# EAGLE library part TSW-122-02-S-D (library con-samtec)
THROUGH-HOLE .025" SQ POST HEADER Source: Samtec TSW.pdf
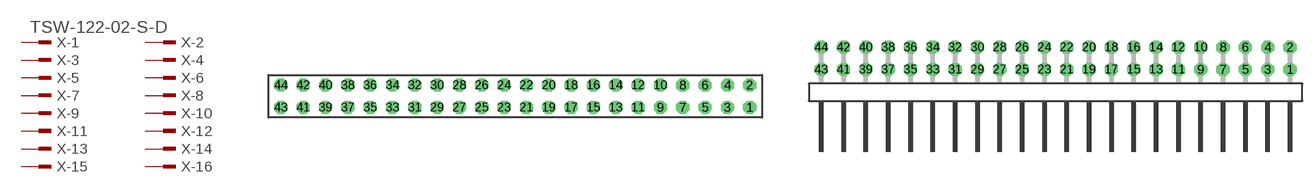
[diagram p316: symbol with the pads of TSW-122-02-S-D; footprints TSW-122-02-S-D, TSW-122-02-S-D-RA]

Designator prefix X; gates -1=MPINV -2=MPIN -3=MPIN -4=MPIN -5=MPIN -6=MPIN -7=MPIN -8=MPIN -9=MPIN -10=MPIN -11=MPIN -12=MPIN -13=MPIN -14=MPIN -15=MPIN -16=MPIN -17=MPIN -18=MPIN -19=MPIN -20=MPIN -21=MPIN -22=MPIN -23=MPIN -24=MPIN -25=MPIN -26=MPIN -27=MPIN -28=MPIN -29=MPIN -30=MPIN -31=MPIN -32=MPIN -33=MPIN -34=MPIN -35=MPIN -36=MPIN -37=MPIN -38=MPIN -39=MPIN -40=MPIN -41=MPIN -42=MPIN -43=MPIN -44=MPIN

## TSW-122-02-S-D (OC_FARNELL: unknown; OC_NEWARK: unknown)  [TSW-122-02-S-D]
1  -1:1  pas
2  -2:1  pas
3  -3:1  pas
4  -4:1  pas
5  -5:1  pas
6  -6:1  pas
7  -7:1  pas
8  -8:1  pas
9  -9:1  pas
10  -10:1  pas
11  -11:1  pas
12  -12:1  pas
13  -13:1  pas
14  -14:1  pas
15  -15:1  pas
16  -16:1  pas
17  -17:1  pas
18  -18:1  pas
19  -19:1  pas
20  -20:1  pas
21  -21:1  pas
22  -22:1  pas
23  -23:1  pas
24  -24:1  pas
25  -25:1  pas
26  -26:1  pas
27  -27:1  pas
28  -28:1  pas
29  -29:1  pas
30  -30:1  pas
31  -31:1  pas
32  -32:1  pas
33  -33:1  pas
34  -34:1  pas
35  -35:1  pas
36  -36:1  pas
37  -37:1  pas
38  -38:1  pas
39  -39:1  pas
40  -40:1  pas
41  -41:1  pas
42  -42:1  pas
43  -43:1  pas
44  -44:1  pas

## TSW-122-02-S-D-RA (OC_FARNELL: unknown; OC_NEWARK: unknown)  [TSW-122-02-S-D-RA]
Pads as for TSW-122-02-S-D

## Footprint TSW-122-02-S-D (pad centres in mm)
THROUGH-HOLE .025" SQ POST HEADER Source: Samtec TSW.pdf
drill 1 pad 1.5 octagon: 1 26.67,-1.27; 2 26.67,1.27; 3 24.13,-1.27; 4 24.13,1.27; 5 21.59,-1.27; 6 21.59,1.27; 7 19.05,-1.27; 8 19.05,1.27; 9 16.51,-1.27; 10 16.51,1.27; 11 13.97,-1.27; 12 13.97,1.27; 13 11.43,-1.27; 14 11.43,1.27; 15 8.89,-1.27; 16 8.89,1.27; 17 6.35,-1.27; 18 6.35,1.27; 19 3.81,-1.27; 20 3.81,1.27; 21 1.27,-1.27; 22 1.27,1.27; 23 -1.27,-1.27; 24 -1.27,1.27; 25 -3.81,-1.27; 26 -3.81,1.27; 27 -6.35,-1.27; 28 -6.35,1.27; 29 -8.89,-1.27; 30 -8.89,1.27; 31 -11.43,-1.27; 32 -11.43,1.27; 33 -13.97,-1.27; 34 -13.97,1.27; 35 -16.51,-1.27; 36 -16.51,1.27; 37 -19.05,-1.27; 38 -19.05,1.27; 39 -21.59,-1.27; 40 -21.59,1.27; 41 -24.13,-1.27; 42 -24.13,1.27; 43 -26.67,-1.27; 44 -26.67,1.27

## Footprint TSW-122-02-S-D-RA (pad centres in mm)
THROUGH-HOLE .025" SQ POST HEADER Source: Samtec TSW.pdf
drill 1 pad 1.5 octagon: 1 26.67,1.524; 2 26.67,4.064; 3 24.13,1.524; 4 24.13,4.064; 5 21.59,1.524; 6 21.59,4.064; 7 19.05,1.524; 8 19.05,4.064; 9 16.51,1.524; 10 16.51,4.064; 11 13.97,1.524; 12 13.97,4.064; 13 11.43,1.524; 14 11.43,4.064; 15 8.89,1.524; 16 8.89,4.064; 17 6.35,1.524; 18 6.35,4.064; 19 3.81,1.524; 20 3.81,4.064; 21 1.27,1.524; 22 1.27,4.064; 23 -1.27,1.524; 24 -1.27,4.064; 25 -3.81,1.524; 26 -3.81,4.064; 27 -6.35,1.524; 28 -6.35,4.064; 29 -8.89,1.524; 30 -8.89,4.064; 31 -11.43,1.524; 32 -11.43,4.064; 33 -13.97,1.524; 34 -13.97,4.064; 35 -16.51,1.524; 36 -16.51,4.064; 37 -19.05,1.524; 38 -19.05,4.064; 39 -21.59,1.524; 40 -21.59,4.064; 41 -24.13,1.524; 42 -24.13,4.064; 43 -26.67,1.524; 44 -26.67,4.064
